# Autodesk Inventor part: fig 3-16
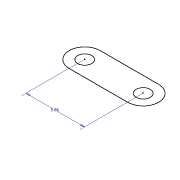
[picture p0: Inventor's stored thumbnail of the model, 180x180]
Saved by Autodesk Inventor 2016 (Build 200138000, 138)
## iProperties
Created: 2009-11
Part Number: fig 3-16
Document SubType Name: Modeling
Designer: Sham
Density: 1 g/cm^3
Material: Generic
Appearance: Default
Author: Sham
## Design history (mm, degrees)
sketch "Sketch1"
  geometry: L1 (4.59, -0.041)-(10.25, -0.041); L2 (4.59, -3.041)-(10.25, -3.041); C1 r 0.679 at (4.59, -1.541); C2 r 0.679 at (10.25, -1.541); A1 r 1.5 centre (4.59, -1.541) between (4.59, -0.041) and (4.59, -3.041); A2 r 1.5 centre (10.25, -1.541) between (10.25, -3.041) and (10.25, -0.041)
  constraints: 4 centre point, 4 end point, 4 point on circle, 2 coincident, 2 horizontal, 2 tangent, 1 equal radius
  dimensions: "d2" = 5.66 dimension on A1.centre A1 A2.centre A2 L1.start L1.end L1 L2.start L2.end L2 C1.centre C1 C2.centre C2; "d2" = 5.66 distance of A2.centre A1.centre
